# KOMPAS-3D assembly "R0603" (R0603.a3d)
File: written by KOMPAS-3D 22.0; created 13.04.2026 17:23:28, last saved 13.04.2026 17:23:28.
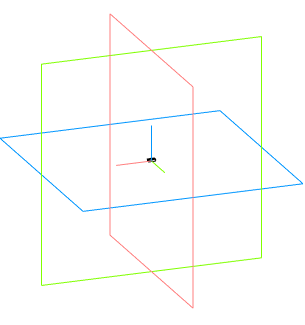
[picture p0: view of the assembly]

Document properties: Автор: Andrey; Полное имя файла: C:\Users\User1\Documents\R0603.a3d

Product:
- Component [detail]: ERJ3RSFR10V  | qty 1  | source file: ERJ3RSFR10V.m3d
- Part/product: R0603
    Комментарий: R0603

Referenced files in C:\Users\User1\Documents\: ERJ3RSFR10V.m3d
